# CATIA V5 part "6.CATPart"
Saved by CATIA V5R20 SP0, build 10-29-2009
Part number: 6
Bounding box of the stored display mesh (mm): x -12.5 to 12.5, y -12.5 to 12.5, z -20 to 30
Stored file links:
  E:\Ehsan\Amoozesh\CATIA\CATIA Course\Advanced\Exercises\DMU Kinematic\11\6.CATPart
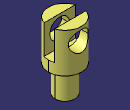
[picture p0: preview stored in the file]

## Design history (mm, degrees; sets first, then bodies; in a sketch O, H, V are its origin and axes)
Body1 (main body)
  Sketch1 on xy-plane, origin (0, 0, 0), H (1, 0, 0), V (0, 1, 0)
    circle A1 centre (0, 0) radius 12.5
    radius A1 = 12.5
  Pad1: profile Sketch1, direction (0, 0, 1), length 30
  Sketch2 on end face of Pad1, origin (0, 0, 30), H (1, 0, 0), V (0, 1, 0)
    line L1 (11.8427, -4) -> (-11.8427, -4)
    line L2 (-11.8427, 4) -> (11.8427, 4)
    projected circle E1 centre (0, 0) radius 12.5 from edge [face of Pad1 from Sketch1.A1 | end face of Pad1]
    projected arc E2 centre (0, 0) radius 12.5 from (-11.8427, 4) to (-11.8427, -4) ccw from edge [face of Pad1 from Sketch1.A1 | end face of Pad1]
    projected arc E3 centre (0, 0) radius 12.5 from (11.8427, -4) to (11.8427, 4) ccw from edge [face of Pad1 from Sketch1.A1 | end face of Pad1]
    point P1 (11.8427, 4)
    point P2 (-11.8427, 4)
    point P4 (11.8427, -4)
    point P5 (-11.8427, 4)
    point P6 (11.8427, -4)
    point P7 (11.8427, 4)
    distance L2 L1 = 8
    horizontal: L1 H, L2 H
    equidistance: L1 L2 O
    coincidence: L2 P1, L2 P2, L1 P4, E1 P5, E1 P6, E1 P7, P1 P7, P2 P5, P4 P6
  Pocket1: profile Sketch2, direction (0, 0, -1), length 22
  Sketch3 on start face of Pad1, origin (0, 0, 0), H (1, 0, 0), V (0, -1, 0)
    circle A1 centre (0, 0) radius 7.5
    radius A1 = 7.5
  Pad2: profile Sketch3, direction (0, 0, -1), length 20
  Sketch4 on zx-plane, origin (0, 0, 0), H (-1, 0, 0), V (0, 0, 1)
    circle A1 centre (0, 20.3842) radius 7.5
    point P1 (0, 20.3842)
    radius A1 = 7.5
    coincidence: P1 V
  Pocket2: profile Sketch4, direction (0, -1, 0), through (limit type 6), opposite side through (limit type 6)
